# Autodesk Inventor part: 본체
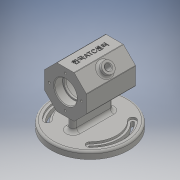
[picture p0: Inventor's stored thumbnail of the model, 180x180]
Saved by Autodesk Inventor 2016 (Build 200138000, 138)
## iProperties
Created: 2017-06
Part Number: 본체
Material: 일반
Document SubType Name: Modeling
Designer: USER
Density: 1 g/cm^3
Appearance: 기본값
Author: USER
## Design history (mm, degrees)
sketch "스케치1"
  geometry: L1 (0, 0)-(0, 30); L2 (0, 0)-(-12.426, 30); L3 (0, 0)-(12.426, 30); L4 (0, 0)-(12.426, -30); L5 (0, 0)-(-12.426, -30); L6 (0, 0)-(30, 12.426); L7 (0, 0)-(30, -12.426); L8 (0, 0)-(-30, 12.426); L9 (0, 0)-(-30, -12.426); L10 (0, 0)-(30, 0); L11 (0, 0)-(-30, 0); L12 (0, 0)-(0, -30); L13 (30, 12.426)-(30, -12.426); L14 (-12.426, -30)-(12.426, -30); L15 (-30, 12.426)-(-30, -12.426); L16 (-12.426, 30)-(12.426, 30); L17 (-12.426, 30)-(-30, 12.426); L18 (12.426, 30)-(30, 12.426); L19 (30, -12.426)-(12.426, -30); L20 (-12.426, -30)-(-30, -12.426); A1 r 30 centre (0, 0) between (0, 30) and (-30, 0); 7 further points
  constraints: 40 end point, 4 horizontal, 4 point on circle, 4 point on line, 4 vertical, 3 horizontal alignment, 2 vertical alignment, 1 centre point, 1 coincident, 1 perpendicular
  dimensions: "d0" = 60 diameter of A1; "d1" = 22.5 deg angle of L1 L2; "d2" = 22.5 deg angle of L1 L3; "d4" = 22.5 deg angle of L11 L8; "d5" = 22.5 deg angle of L11 L9; "d6" = 22.5 deg angle of L12 L5; "d7" = 22.5 deg angle of L4 L12; "d8" = 22.5 deg angle of L10 L7
extrude "돌출1" new body sketch "스케치1" distance "d9" = 70; taper "d10" = 0 deg
sketch "스케치2"
  geometry: L1 (0, 0)-(0, 70); L2 (-12.426, 0)-(-30, 0) reference; L3 (-16, 0)-(-16, 12); L4 (-16, 12)-(-14, 12); L5 (-14, 12)-(-14, 15); L6 (-14, 15)-(-25, 15); L7 (-25, 15)-(-25, 55); L8 (-25, 55)-(-14, 55); L9 (-14, 55)-(-14, 58); L10 (-14, 58)-(-16, 58); L11 (-16, 58)-(-16, 70); L12 (-12.426, 70)-(-30, 70) reference; L13 (-16, 70)-(0, 70); L14 (-16, 0)-(0, 0)
  constraints: 24 end point, 7 perpendicular, 3 point on line, 3 vertical, 1 horizontal, 1 parallel
  dimensions: "d11" = 32 diameter of L3 L1; "d12" = 32 diameter of L11 L1; "d13" = 28 diameter of L5 L1; "d14" = 50 diameter of L7 L1; "d15" = 12 distance of L3.start L3.end; "d16" = 12 distance of L10.end L11.end; "d17" = 40 distance of L6.end L7.end; "d18" = 3 distance of L8.end L9.end
revolve "회전1" sketch "스케치2" stored, may be unused: angle "d19" = 90 deg
sketch "스케치3" dims "d20" = 46
  geometry: 3 further points
  constraints: 2 coincident, 2 horizontal alignment, 2 other
hole "구멍1" sketch "스케치3" at (-23, 0) diameter "d21" = 3.242; stored, may be unused: countersink angle "d25" = 90 deg, drill point angle "d27" = 118 deg; dims "d22" = 8, "d23" = 4, "d24" = 2, "d26" = 10
node "작업 평면1"
chamfer "모따기1" distance "d31" = 1; stored, may be unused: second distance "d32" = 2, angle "d33" = 45 deg
fillet "모깎기1" dims "d34" = 3
fillet "모깎기2" dims "d35" = 0.3
node "작업 평면2"
sketch "스케치4"
  geometry: L1 (0, 30)-(70, 30) reference; C1 r 55 at (35, 0); 2 further points
  constraints: 1 centre point, 1 horizontal alignment, 1 midpoint, 1 vertical alignment
  dimensions: "d37" = 110 diameter of C1
extrude "돌출2" join sketch "스케치4" distance "d38" = 10; taper "d39" = 0 deg
sketch "스케치5"
  geometry: L1 (0, -24)-(0, 24); L2 (5, -24)-(5, 24); L3 (-5, 24)-(-5, -24); C1 r 55 at (0, 0) reference; A1 r 5 centre (0, -24) between (-5, -24) and (5, -24); A2 r 5 centre (0, 24) between (5, 24) and (-5, 24); 2 further points
  constraints: 8 end point, 4 point on circle, 4 tangent, 2 centre point, 1 coincident, 1 midpoint, 1 parallel, 1 vertical, 1 vertical alignment
  dimensions: "d40" = 5 radius of A1; "d41" = 48 distance of L1.end L1.start
extrude "돌출3" join sketch "스케치5" stored distance "d42" = 10; taper "d43" = 0 deg
fillet "모깎기3" dims "d44" = 5
sketch "스케치6"
  geometry: L1 (0, 0)-(30.406, 30.406); L2 (0, 0)-(72.385, 0); L3 (0, 0)-(-55, 0); L4 (0, 0)-(30.406, -30.406); L5 (0, 0)-(-30.406, -30.406); L6 (0, 0)-(-30.406, 30.406); A1 r 5 centre (30.406, -30.406) between (26.87, -26.87) and (33.941, -33.941); A2 r 5 centre (30.406, 30.406) between (33.941, 33.941) and (26.87, 26.87); A3 r 5 centre (-30.406, 30.406) between (-26.87, 26.87) and (-33.941, 33.941); A4 r 5 centre (-30.406, -30.406) between (-33.941, -33.941) and (-26.87, -26.87); A5 r 38 centre (0, 0) between (-26.87, 26.87) and (-26.87, -26.87); A6 r 38 centre (0, 0) between (26.87, -26.87) and (26.87, 26.87); A7 r 48 centre (0, 0) between (-33.941, 33.941) and (-33.941, -33.941); A8 r 48 centre (0, 0) between (33.941, -33.941) and (33.941, 33.941); 1 further point
  constraints: 16 point on circle, 12 end point, 8 centre point, 5 point on line, 3 coincident, 2 horizontal, 1 horizontal alignment, 1 other
  dimensions: "d49" = 45 deg angle of L2 L1; "d51" = 10 diameter of A1; "d52" = 10 diameter of A2; "d57" = 10 diameter of A3; "d58" = 10 diameter of A4; "d59" = 45 deg angle of L2 L4; "d60" = 45 deg angle of L3 L5; "d61" = 45 deg angle of L6 L3; "d62" = 38 radius of A6; "d63" = 48 radius of A8; "d64" = 38 radius of A5; "d65" = 48 radius of A7
extrude "돌출4" cut sketch "스케치6" distance "d66" = 3; taper "d67" = 0 deg
sketch "스케치7"
  geometry: L1 (0, 0)-(69.77, 0); L2 (0, 0)-(30.406, 30.406); L3 (0, 0)-(-74.571, 0); L4 (0, 0)-(30.406, -30.406); L5 (0, 0)-(-30.406, -30.406); L6 (0, 0)-(-30.406, 30.406); C1 r 55 at (0, 0) reference; A1 r 2 centre (30.406, 30.406) between (31.82, 31.82) and (28.991, 28.991); A2 r 2 centre (30.406, -30.406) between (28.991, -28.991) and (31.82, -31.82); A3 r 2 centre (-30.406, -30.406) between (-31.82, -31.82) and (-28.991, -28.991); A4 r 2 centre (-30.406, 30.406) between (-28.991, 28.991) and (-31.82, 31.82); A5 r 41 centre (0, 0) between (-28.991, 28.991) and (-28.991, -28.991); A6 r 41 centre (0, 0) between (28.991, -28.991) and (28.991, 28.991); A7 r 45 centre (0, 0) between (-31.82, 31.82) and (-31.82, -31.82); A8 r 45 centre (0, 0) between (31.82, -31.82) and (31.82, 31.82); 1 further point
  constraints: 16 point on circle, 12 end point, 8 centre point, 7 coincident, 2 horizontal, 1 horizontal alignment, 1 vertical alignment
  dimensions: "d70" = 45 deg angle of L1 L2; "d73" = 45 deg angle of L1 L4; "d74" = 45 deg angle of L3 L5; "d75" = 45 deg angle of L6 L3; "d76" = 4 diameter of A1; "d77" = 4 diameter of A2; "d78" = 4 diameter of A3; "d79" = 4 diameter of A4; "d82" = 41 radius of A6; "d83" = 45 radius of A8; "d84" = 41 radius of A5; "d85" = 45 radius of A7; "d86" = 30.40559 distance from line of L1 L2.end
extrude "돌출5" cut sketch "스케치7" distance "d87" = 20; taper "d88" = 0 deg
node "작업 평면3"
sketch "스케치8"
  geometry: L1 (0, 0)-(-26.163, -26.163); L2 (0, 0)-(-40.912, 0)
  constraints: 4 end point, 1 horizontal
  dimensions: "d89" = 45 deg angle of L2 L1; "d90" = 37 distance of L1.start L1.end
node "작업 평면4"
sketch "스케치9"
  geometry: L1 (-35, 12.426)-(-35, -12.426) reference; L2 (-35, -12.426)-(35, -12.426) reference; L3 (35, 12.426)-(35, -12.426) reference; L4 (-35, 12.426)-(35, 12.426) reference; C1 r 8 at (0, 0); 4 further points
  constraints: 2 midpoint, 1 centre point, 1 coincident, 1 horizontal alignment, 1 vertical alignment
  dimensions: "d91" = 16 diameter of C1
extrude "돌출6" join sketch "스케치9" stored distance "d92" = 20; taper "d93" = 0 deg
sketch "스케치11"
  geometry: C1 r 4 at (0, 0); C2 r 8 at (0, 0) reference; 1 further point
  constraints: 2 coincident, 1 centre point
  dimensions: "d94" = 8 diameter of C1
extrude "돌출7" cut sketch "스케치11" distance "d95" = 30; taper "d96" = 0 deg
fillet "모깎기4" dims "d97" = 3
chamfer "모따기2" distance "d98" = 1; stored, may be unused: second distance "d99" = 2, angle "d100" = 45 deg
fillet "모깎기5" dims "d101" = 3
fillet "모깎기6" dims "d102" = 1
sketch "스케치12"
  geometry: L1 (-17.695, 0)-(-0.707, 0) reference; 2 further points
  constraints: 1 other
  dimensions: "d103" = 35 distance from line of L1 point (12.305, 35); "d104" = 30 horizontal distance of point (12.305, 35) L1.start
feature "엠보싱1" sketch "스케치12" dims "d0" = 60, "d1" = 22.5 deg, "d2" = 22.5 deg, "d4" = 22.5 deg, "d5" = 22.5 deg, "d6" = 22.5 deg, "d7" = 22.5 deg, "d8" = 22.5 deg, "d105" = 0.5, "d106" = 0
node "작업 평면5"
node "솔리드1"
pattern_circular "원형 패턴1" dims angle "d29" = 360 deg
mirror "대칭1"
node "투영된 루프1"
node "투영된 루프3"
node "투영된 루프4"
other parameters: "d36" = -62, "d47" = 86, "d48" = 45 deg, "d53" = 96, "d54" = 76, "d55" = 45 deg, "d56" = 45 deg, "d68" = 86, "d69" = 45 deg, "d71" = 45 deg, "d72" = 45 deg, "d81" = 82, "d107" = 2
